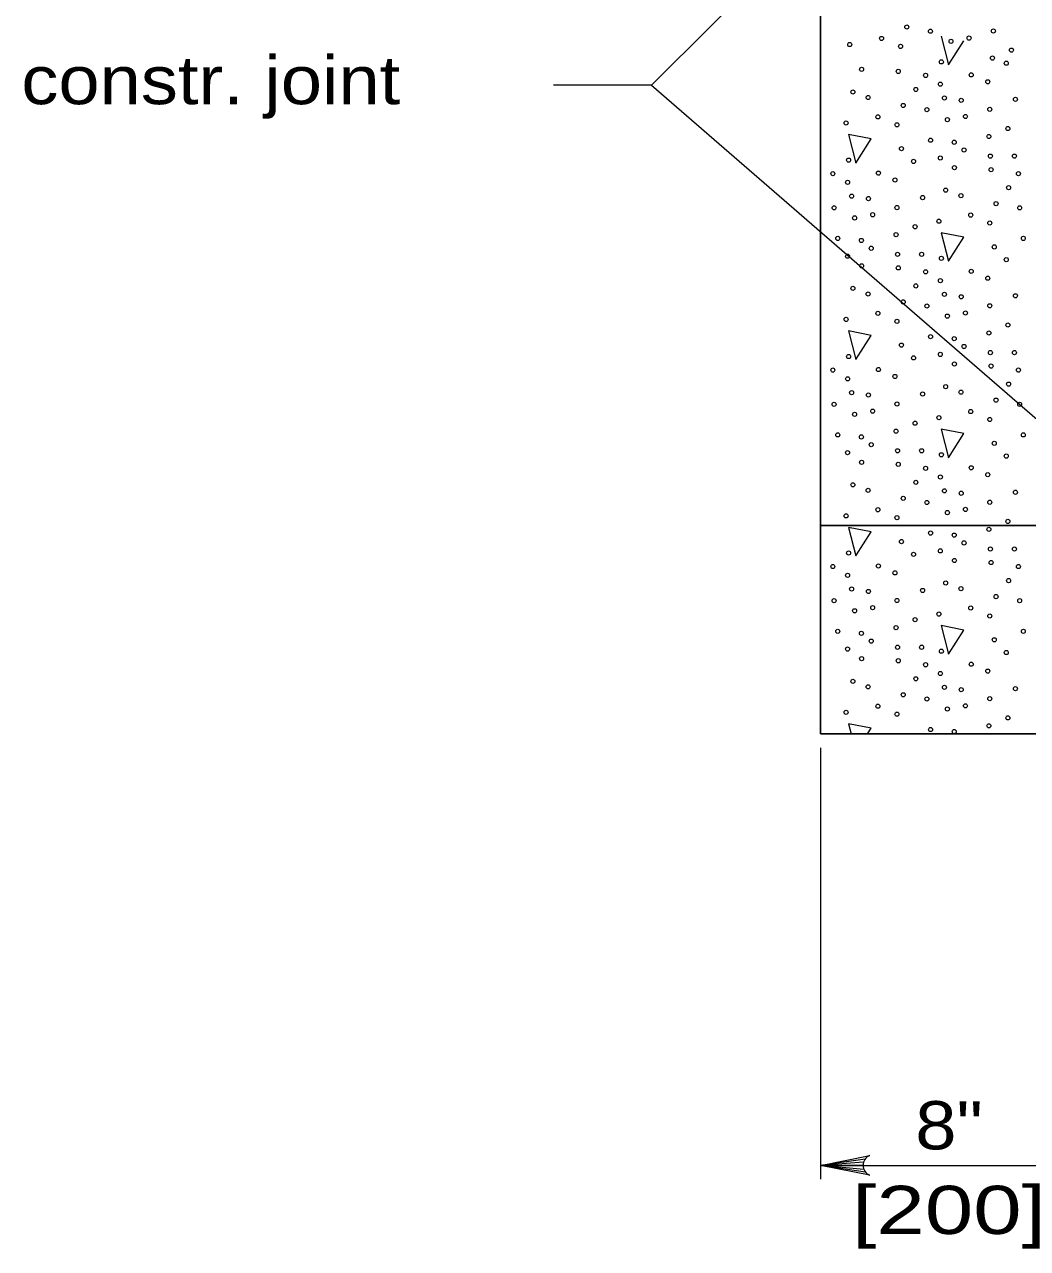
# Model space of a CAD drawing. Extents: x 1352.5 to 1386.5, y 735.9 to 779.9.
# Drawn here: x 1373.002 to 1376.249, y 768.997 to 772.96 of the extents above; entities that cross this region are included whole.
import ezdxf
from ezdxf.enums import TextEntityAlignment as Align

# ---------------------------------------------------------------- set-up
doc = ezdxf.new("R2010")
doc.units = 0
doc.header["$LTSCALE"] = 0.062
doc.layers.add('1', color=7, linetype='Continuous', lineweight=13)

msp = doc.modelspace()

# ---------------------------------------------------------------- linework, layer by layer
at = {"layer": '1'}
for p, q in [((1375.96933, 772.92133), (1375.99358, 772.82917)), ((1375.99358, 772.82917), (1376.043, 772.90692)), ((1375.03217, 772.76333), (1374.71417, 772.76333)), ((1375.66892, 770.69517), (1375.6775, 770.6625)), ((1375.57867, 770.61742), (1375.57867, 769.22067)), ((1375.72283, 769.28583), (1375.57867, 769.26567)), ((1375.718, 769.27583), (1375.57867, 769.26567)), ((1375.7165, 769.26567), (1375.57867, 769.26567)), ((1375.719, 769.25275), (1375.57867, 769.26567)), ((1375.72458, 769.24333), (1375.57867, 769.26567))]:
    msp.add_line(p, q, dxfattribs=at)
at = {"layer": '1', "lineweight": 25}
msp.add_line((1378.65958, 771.33708), (1375.57867, 771.33708), dxfattribs=at)
for points in [[(1375.57867, 774.88233), (1375.57867, 772.89383), (1375.57867, 770.66242)], [(1375.57867, 770.66242), (1380.0815, 770.66242), (1380.0815, 771.20208), (1379.81392, 771.20208)]]:
    msp.add_lwpolyline(points, dxfattribs=at)
at = {"layer": '1'}
for points in [[(1376.80792, 774.53058), (1375.03217, 772.76333), (1376.67692, 771.33608)], [(1375.73092, 770.6625), (1375.74267, 770.68075), (1375.66892, 770.69517)], [(1375.73792, 769.23383), (1375.57867, 769.26567), (1375.73792, 769.2975)], [(1375.57867, 769.26567), (1376.10667, 769.26567), (1376.42825, 769.26567), (1377.489, 769.26567)]]:
    msp.add_lwpolyline(points, dxfattribs=at)
for points in [[(1375.66892, 772.60325), (1375.69317, 772.51108), (1375.74267, 772.58892)], [(1375.96933, 772.28525), (1375.99358, 772.19308), (1376.043, 772.27092)], [(1375.66892, 771.96725), (1375.69317, 771.87508), (1375.74267, 771.95292)], [(1375.96933, 771.64925), (1375.99358, 771.557), (1376.043, 771.63483)], [(1375.66892, 771.33117), (1375.69317, 771.23908), (1375.74267, 771.31683)], [(1375.96933, 771.01325), (1375.99358, 770.921), (1376.043, 770.99883)]]:
    msp.add_lwpolyline(points, close=True, dxfattribs=at)
msp.add_arc((1375.75079, 769.2657), 0.03438, 112.08782, 247.91395, dxfattribs=at)
for centre in [(1375.8582, 772.95132), (1375.77625, 772.91438), (1375.9347, 772.93786), (1376.05961, 772.91555), (1376.13831, 772.93865), (1375.67327, 772.89461), (1375.83793, 772.88862), (1376.00118, 772.90521), (1376.19693, 772.87659), (1375.97013, 772.8385), (1376.13535, 772.85083), (1376.18024, 772.83421), (1375.71195, 772.81417), (1375.8306, 772.8076), (1375.91906, 772.79472), (1376.06665, 772.79641), (1375.96687, 772.76636), (1376.12017, 772.7741), (1375.68357, 772.74119), (1375.73303, 772.72317), (1375.88737, 772.74919), (1375.97989, 772.72173), (1376.03421, 772.71394), (1376.20968, 772.71718), (1375.84657, 772.69741), (1375.92307, 772.68394), (1376.12668, 772.68474), (1375.66164, 772.64069), (1375.76462, 772.66046), (1375.8263, 772.6347), (1375.98955, 772.65129), (1376.04798, 772.66163), (1376.12372, 772.59691), (1376.1853, 772.62267), (1375.84092, 772.55743), (1375.93498, 772.58493), (1376.01153, 772.57831), (1376.04342, 772.55313), (1375.66975, 772.52048), (1375.87986, 772.51619), (1375.96662, 772.52737), (1376.12858, 772.53336), (1376.20648, 772.53336), (1375.61868, 772.4767), (1375.76627, 772.4784), (1376.01233, 772.49616), (1376.13098, 772.48958), (1376.21944, 772.4767), (1375.6665, 772.44835), (1375.81979, 772.45609), (1375.67951, 772.40372), (1375.73383, 772.39593), (1375.9093, 772.39916), (1375.98395, 772.42317), (1376.03341, 772.40515), (1376.18775, 772.43117), (1375.62269, 772.36593), (1375.8263, 772.36672), (1376.14695, 772.37939), (1376.22345, 772.36593), (1375.68917, 772.33328), (1375.7476, 772.34361), (1375.96202, 772.32268), (1376.065, 772.34245), (1376.12668, 772.31669), (1375.82334, 772.2789), (1375.88492, 772.30466), (1375.6346, 772.26692), (1375.71115, 772.26029), (1376.14129, 772.23941), (1376.23536, 772.26692), (1375.66624, 772.20936), (1375.74304, 772.23512), (1375.8282, 772.21535), (1375.9061, 772.21535), (1375.97013, 772.20247), (1376.18024, 772.19818), (1375.71195, 772.17814), (1375.8306, 772.17157), (1375.91906, 772.15869), (1376.06665, 772.16039), (1375.96687, 772.13033), (1376.12017, 772.13807), (1375.68357, 772.10516), (1375.73303, 772.08714), (1375.88737, 772.11316), (1375.97989, 772.0857), (1376.03421, 772.07791), (1376.20968, 772.08115), (1375.84657, 772.06138), (1375.92307, 772.04791), (1376.12668, 772.04871), (1375.66164, 772.00466), (1375.76462, 772.02443), (1375.8263, 771.99867), (1375.98955, 772.01526), (1376.04798, 772.0256), (1376.12372, 771.96088), (1376.1853, 771.98664), (1375.84092, 771.9214), (1375.93498, 771.94891), (1376.01153, 771.94228), (1375.66975, 771.88445), (1375.87986, 771.88016), (1375.96662, 771.89134), (1376.04342, 771.9171), (1376.12858, 771.89733), (1376.20648, 771.89733), (1375.61868, 771.84067), (1375.76627, 771.84237), (1376.01233, 771.86013), (1376.13098, 771.85355), (1376.21944, 771.84067), (1375.6665, 771.81232), (1375.81979, 771.82006), (1375.67951, 771.76769), (1375.9093, 771.76313), (1375.98395, 771.78714), (1376.03341, 771.76912), (1376.18775, 771.79514), (1375.62269, 771.7299), (1375.73383, 771.7599), (1375.8263, 771.73069), (1376.14695, 771.74336), (1376.22345, 771.7299), (1375.68917, 771.69725), (1375.7476, 771.70758), (1375.96202, 771.68665), (1376.065, 771.70642), (1375.82334, 771.64287), (1375.88492, 771.66863), (1376.12668, 771.68066), (1375.6346, 771.63089), (1375.71115, 771.62426), (1376.14129, 771.60338), (1376.23536, 771.63089), (1375.66624, 771.57333), (1375.74304, 771.59909), (1375.8282, 771.57932), (1375.9061, 771.57932), (1375.97013, 771.56644), (1375.71195, 771.54211), (1375.8306, 771.53554), (1375.91906, 771.52266), (1376.06665, 771.52436), (1376.18024, 771.56215), (1375.96687, 771.4943), (1376.12017, 771.50204), (1375.68357, 771.46913), (1375.73303, 771.45111), (1375.88737, 771.47713), (1375.97989, 771.44967), (1376.20968, 771.44512), (1375.84657, 771.42535), (1375.92307, 771.41188), (1376.03421, 771.44188), (1376.12668, 771.41268), (1375.66164, 771.36863), (1375.76462, 771.3884), (1375.98955, 771.37923), (1376.04798, 771.38957), (1375.8263, 771.36264), (1376.12372, 771.32485), (1376.1853, 771.35061), (1375.84092, 771.28537), (1375.93498, 771.31288), (1376.01153, 771.30625), (1375.66975, 771.24842), (1375.96662, 771.25531), (1376.04342, 771.28107), (1376.12858, 771.2613), (1376.20648, 771.2613), (1375.76627, 771.20634), (1375.87986, 771.24413), (1376.01233, 771.2241), (1376.13098, 771.21752), (1375.61868, 771.20464), (1375.6665, 771.17629), (1375.81979, 771.18403), (1376.21944, 771.20464), (1375.67951, 771.13166), (1375.9093, 771.1271), (1375.98395, 771.15111), (1376.03341, 771.13309), (1376.18775, 771.15912), (1375.62269, 771.09387), (1375.73383, 771.12387), (1375.8263, 771.09466), (1376.14695, 771.10733), (1376.22345, 771.09387), (1375.68917, 771.06122), (1375.7476, 771.07156), (1375.96202, 771.05062), (1376.065, 771.07039), (1375.88492, 771.0326), (1376.12668, 771.04463), (1375.6346, 770.99486), (1375.71115, 770.98824), (1375.82334, 771.00684), (1376.23536, 770.99486), (1375.66624, 770.9373), (1375.74304, 770.96306), (1375.8282, 770.94329), (1375.9061, 770.94329), (1375.97013, 770.93041), (1376.14129, 770.96735), (1375.71195, 770.90608), (1375.8306, 770.89951), (1376.18024, 770.92612), (1375.91906, 770.88663), (1375.96687, 770.85827), (1376.06665, 770.88833), (1376.12017, 770.86601), (1375.68357, 770.8331), (1375.73303, 770.81508), (1375.88737, 770.8411), (1375.97989, 770.81365), (1375.84657, 770.78932), (1375.92307, 770.77585), (1376.03421, 770.80585), (1376.12668, 770.77665), (1376.20968, 770.80909), (1375.66164, 770.7326), (1375.76462, 770.75237), (1375.98955, 770.7432), (1376.04798, 770.75354), (1375.8263, 770.72662), (1376.1853, 770.71458), (1375.93498, 770.67685), (1376.01153, 770.67022), (1376.12372, 770.68882)]:
    msp.add_ellipse(centre, major_axis=(0, 0.0068), ratio=0.944544, dxfattribs=at)

# ---------------------------------------------------------------- texts
at = {"layer": '1', "width": 1.15}
msp.add_text('constr. joint', height=0.156, dxfattribs=at).set_placement((1372.99183, 772.7015))
at = {"layer": '1'}
for s, width, p in [('8"', 1.15, (1375.99483, 769.31758)), ('[200]', 1.35, (1375.99483, 769.04358))]:
    msp.add_text(s, height=0.156, dxfattribs=dict(at, width=width)).set_placement(p, align=Align.CENTER)

doc.saveas('drawing.dxf')
